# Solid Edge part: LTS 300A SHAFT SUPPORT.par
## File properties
Author: davee
Template: Normal.par
Last saved by: davee
Revision: 6
Application: Solid Edge
Accuracy: 0.990
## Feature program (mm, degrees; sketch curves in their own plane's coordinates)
sketch for "unnamed Protrusion 1" #1 plane through (0, 0, 0) normal (0, 0, 1) x-axis (1, 0, 0)
  line (9.5, -14.5) -> (28.5, -14.5)
  line (28.5, -14.5) -> (28.5, 10)
  line (28.5, 10) -> (9.5, 10)
  line (9.5, 10) -> (9.5, -14.5)
sketch for "unnamed Protrusion 1" #2 plane through (0, 0, 0) normal (0, 0, 1) x-axis (1, 0, 0)
  line (-28.5, -10) -> (-9.5, -10)
  line (-9.5, -10) -> (-9.5, 10)
  line (-9.5, 10) -> (-28.5, 10)
  line (-28.5, 10) -> (-28.5, -10)
  dimension (linear) = 9.5
  dimension (linear) = 28.5
  dimension (linear) = 28.5
  dimension (linear) = 28.5
extrude "unnamed Protrusion 1" add finite 13 along +normal
sketch for "ExtrudedProtrusion_2" plane through (-18.5, 0, 13) normal (0, 0, 1) x-axis (1, 0, 0)
  line (-10, 10) -> (47, 10)
  line (47, 2) -> (47, 10)
  line (-10, 2) -> (47, 2)
  line (-10, 10) -> (-10, 2)
extrude "ExtrudedProtrusion_2" add finite 57.5 along +normal
sketch for "unnamed Cutout 1" plane through (0, 2, 41.75) normal (0, -1, 0) x-axis (1, 0, 0)
  circle centre (0, 2.25) radius 10
extrude "unnamed Cutout 1" cut through along -normal
sketch for "ExtrudedCutout_2" plane through (0, 2, 41.75) normal (0, -1, 0) x-axis (1, 0, 0)
  line (2.45, 13.25) -> (6.3509, 13.25)
  line (6.3509, 13.25) -> (12.7017, 2.25)
  line (12.7017, 2.25) -> (6.3509, -8.75)
  line (2.45, -8.75) -> (6.3509, -8.75)
  line (2.45, -7.75) -> (2.45, -8.75)
  line (-2.45, -7.75) -> (2.45, -7.75)
  line (-2.45, -7.75) -> (-2.45, -8.75)
  line (-6.3509, -8.75) -> (-2.45, -8.75)
  line (-12.7017, 2.25) -> (-6.3509, -8.75)
  line (-6.3509, 13.25) -> (-12.7017, 2.25)
  line (-6.3509, 13.25) -> (-2.45, 13.25)
  line (-2.45, 13.25) -> (-2.45, 12.25)
  line (-2.45, 12.25) -> (2.45, 12.25)
  line (2.45, 12.25) -> (2.45, 13.25)
  dimension (linear) = 6.3509
  dimension (linear) = 6.3509
  dimension (linear) = 6.3509
  dimension (linear) = 12.7017
  dimension (linear) = 6.3509
  dimension (linear) = 12.7017
  dimension (linear) = 2.45
  dimension (linear) = 2.45
extrude "ExtrudedCutout_2" cut finite 4 along -normal
sketch for "Hole_1" plane through (-18.5, 0, 0) normal (0, 0, -1) x-axis (1, 0, 0)
  hole centre (35.5, 6.5) bore radius 1.1
hole "Hole_1" diameter 2.2 through
sketch for "unnamed Hole 1" plane through (-18.5, 0, 0) normal (0, 0, -1) x-axis (1, 0, 0)
  hole centre (1.5, 2) bore radius 1.1
hole "unnamed Hole 1" through
sketch for "Hole_3" plane through (-18.5, 0, 0) normal (0, 0, -1) x-axis (1, 0, 0)
  hole centre (1.5, 2) bore radius 2.2
hole "Hole_3" diameter 4.4 finite  VBottomAngle = 118 deg
sketch for "unnamed Hole 2" plane through (-18.5, 0, 0) normal (0, 0, -1) x-axis (1, 0, 0)
  hole centre (35.5, 6.5) bore radius 2.2
hole "unnamed Hole 2" finite
sketch for "Hole_5" plane through (-19, 0, 0) normal (0, 0, -1) x-axis (1, 0, 0)
  hole centre (-2, 2) bore radius 1.65
hole "Hole_5" diameter 3.3 through
sketch for "unnamed Hole 3" plane through (-19, 0, 0) normal (0, 0, -1) x-axis (1, 0, 0)
  hole centre (40, 6.5) bore radius 1.65
hole "unnamed Hole 3" through
sketch for "ExtrudedCutout_3" #1 plane through (-19, -4, 0) normal (0, 0, -1) x-axis (1, 0, 0)
  line (36, 1.5) -> (40, 1.5)
  line (40, 1.5) -> (40, 3.5)
  line (40, 3.5) -> (36, 3.5)
  line (36, 3.5) -> (36, 1.5)
sketch for "ExtrudedCutout_3" #2 plane through (-19, -4, 0) normal (0, 0, -1) x-axis (1, 0, 0)
  line (-2, -3) -> (2, -3)
  line (2, -3) -> (2, -1)
  line (2, -1) -> (-2, -1)
  line (-2, -1) -> (-2, -3)
extrude "ExtrudedCutout_3" cut finite 8 along -normal
sketch for "ExtrudedProtrusion_4" plane through (-19, -4, 13) normal (0, 0, 1) x-axis (1, 0, 0)
  line (5.9213, -0.4) -> (32.0787, -0.4)
  line (32.0787, -0.4) -> (32.0787, 14)
  line (5.9213, 14) -> (32.0787, 14)
  line (5.9213, 14) -> (5.9213, -0.4)
extrude "ExtrudedProtrusion_4" add finite 5.5 along -normal
sketch for "ExtrudedCutout_4" plane through (0, 2, 41.75) normal (0, -1, 0) x-axis (1, 0, 0)
  circle centre (0, -4.25) radius 27
extrude "ExtrudedCutout_4" cut finite 69.85 along +normal
sketch for "ExtrudedCutout_8" plane through (0, 2, 40.5) normal (0, -1, 0) x-axis (1, 0, 0)
  line (25.5, -27.5) -> (28.5, -27.5)
  line (25.5, 3.5) -> (25.5, -27.5)
  line (-25.5, 3.5) -> (-25.5, -27.5)
  line (-28.5, -27.5) -> (-25.5, -27.5)
  line (-28.5, 30) -> (-28.5, -27.5)
  line (-28.5, 30) -> (28.5, 30)
  line (28.5, 30) -> (28.5, -27.4)
extrude "ExtrudedCutout_8" cut finite 4 along -normal
sketch for "ExtrudedProtrusion_5" plane through (0, 6, 41.75) normal (0, -1, 0) x-axis (1, 0, 0)
  line (-25.5, 28.75) -> (-25.5, -28.75)
  line (-25.5, -28.75) -> (-28.5, -28.75)
  line (-28.5, 28.75) -> (-28.5, -28.75)
  line (-28.5, 28.75) -> (-25.5, 28.75)
extrude "ExtrudedProtrusion_5" add finite 20 along +normal
sketch for "ExtrudedCutout_9" plane through (-28.5, -2, 35.25) normal (-1, 0, 0) x-axis (0, -1, 0)
  line (-8, 35.25) -> (6, -15.45)
  line (6, -22.25) -> (6, -15.45)
  line (6, -22.25) -> (18.4691, -22.25)
  dimension (linear) = 6
  dimension (linear) = 6
extrude "ExtrudedCutout_9" cut finite 3 along -normal
sketch for "ExtrudedProtrusion_6" plane through (1.5, 6, 41.75) normal (0, -1, 0) x-axis (1, 0, 0)
  line (24, -28.75) -> (24, 28.75)
  line (24, 28.75) -> (27, 28.75)
  line (27, 28.75) -> (27, -28.75)
  line (27, -28.75) -> (24, -28.75)
extrude "ExtrudedProtrusion_6" add finite 31.75 along +normal
sketch for "ExtrudedCutout_10" plane through (28.5, -7.875, 35.25) normal (1, 0, 0) x-axis (0, 1, 0)
  line (-6.625, -22.25) -> (-4.625, -22.25)
  line (-4.625, -16.07) -> (-4.625, -22.25)
  line (13.875, 35.25) -> (-4.625, -16.07)
  dimension (linear) = 6.625
  dimension (linear) = 4.625
extrude "ExtrudedCutout_10" cut finite 3 along -normal
fillet "Round_1" radius 2
fillet "Round_2" radius 3
fillet "Round_3" radius 0.8
pattern "unnamed Pattern 1" of "Hole_1", "unnamed Hole 1"
pattern "unnamed Pattern 2" of "Hole_3", "unnamed Hole 2"
pattern "unnamed Pattern 3" of "Hole_5", "unnamed Hole 3"
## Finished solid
Body 1: solid body, 89 faces, 205 edges, 116 vertices.
  Faces by surface: plane 43, cylinder 32, sphere 6, torus 4, blend 2, cone 2
  Edges by curve: line 136, circle 59, ellipse 10
Bounding box of the edges (mm; curved faces can reach further): 57.000 x 24.500 x 70.500, from (-28.5, -14.5, 0) to (28.5, 10, 70.5).
Cylindrical faces by radius (mm): R0.8 x3, R1.1 x2, R1.65 x2, R2 x19, R2.2 x2, R3 x2, R10 x1, R25.5 x1
Conical faces (half-angle, radius in mm at the cone's reference point): 59 deg R2.2 x2
Toroidal faces (ring radius, tube radius in mm): R2.2 r0.8 x2, R4 r2 x2
Spherical faces by radius (mm): R2 x6
Planar faces by outward normal: +x 5, +y 3, +z 5, -x 5, -y 11, -z 8, oblique 6
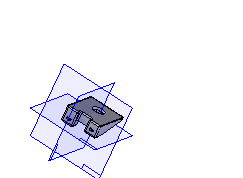
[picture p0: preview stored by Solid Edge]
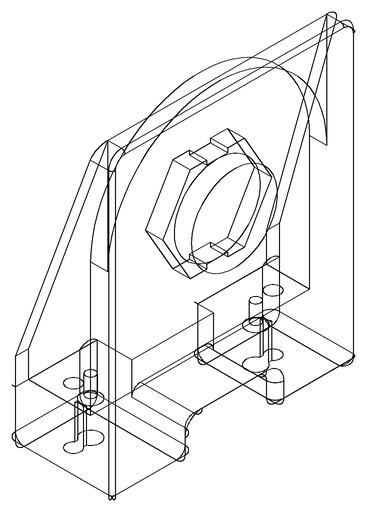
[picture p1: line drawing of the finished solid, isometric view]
